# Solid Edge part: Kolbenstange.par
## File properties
Username: bmolnar
Dokumentum tartalom típus: 0
Author: bmolnar
Last saved by: bmolnar
Revision: 86
Sűrűség: 0,000 kg/m^3
Pontosság: 0,990
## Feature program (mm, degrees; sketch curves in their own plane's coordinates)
base feature "unnamed BaseFeature 1"
sketch for "unnamed Protrusion 1" plane through (33.5, 0, 0) normal (1, 0, 0) x-axis (0, 0, 1)
  circle centre (0, 0) radius 40
extrude "unnamed Protrusion 1" add finite 19.5 along +normal
sketch for "Kihúzás_2" plane through (33.5, 0, 0) normal (1, 0, 0) x-axis (0, 0, 1)
  circle centre (0, 0) radius 40
extrude "Kihúzás_2" add finite 4.5 along -normal
sketch for "Furat_1" plane through (-45, 0, 0) normal (-1, 0, 0) x-axis (0, 0, -1)
  hole centre (0, 0) bore radius 5.053
hole "Furat_1" nominal diameter 12 finite  ThreadDepth = 20 mm
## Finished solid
Body 1: solid body, 15 faces, 21 edges, 8 vertices.
  Faces by surface: plane 8, cylinder 4, cone 2, torus 1
  Edges by curve: circle 11, line 6, ellipse 2, intersection 2
Bounding box of the edges (mm; curved faces can reach further): 98.000 x 80.000 x 80.000, from (-45, -40, -40) to (53, 40, 40).
Cylindrical faces by radius (mm): R5.053 x2, R10 x1, R40 x1
Conical faces (half-angle, radius in mm at the cone's reference point): 45 deg R5.553 x1, 59 deg R2.5265 x1
Toroidal faces (ring radius, tube radius in mm): R8.2 r1.8 x1
Planar faces by outward normal: +x 1, +z 1, -x 3, -z 1, oblique 2
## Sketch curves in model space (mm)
circle centre (33.5, 0, 0) radius 40
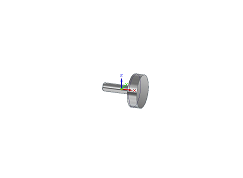
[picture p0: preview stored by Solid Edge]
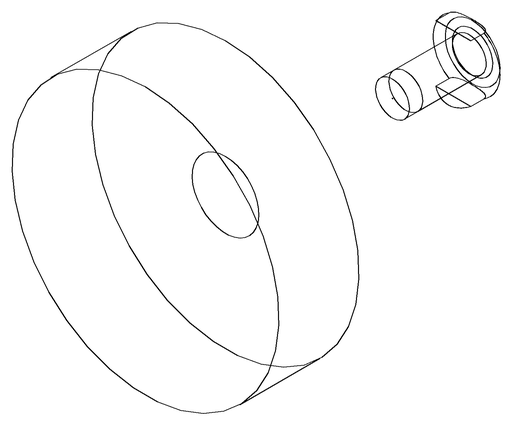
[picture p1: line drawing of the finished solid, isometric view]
